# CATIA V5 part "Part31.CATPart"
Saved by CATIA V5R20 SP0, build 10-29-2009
Part number: 9AE052430-3
Revision: ANY
Definition: UNKNOWN
Nomenclature: 9AE052430-3
Source: Unknown
Bounding box of the stored display mesh (mm): x -14.75 to 14.75, y 0 to 68.999, z -14.75 to 14.75
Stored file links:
  C:\Users\Utente\Desktop\IO LAVORO\3D X SITO CF\CUMSA\3D files AE\AE 062430\Part31.CATPart
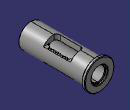
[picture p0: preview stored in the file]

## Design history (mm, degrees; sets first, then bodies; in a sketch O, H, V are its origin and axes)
Body1 "Cortar-Barrer1" (main body)
  Solid1: solid without history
